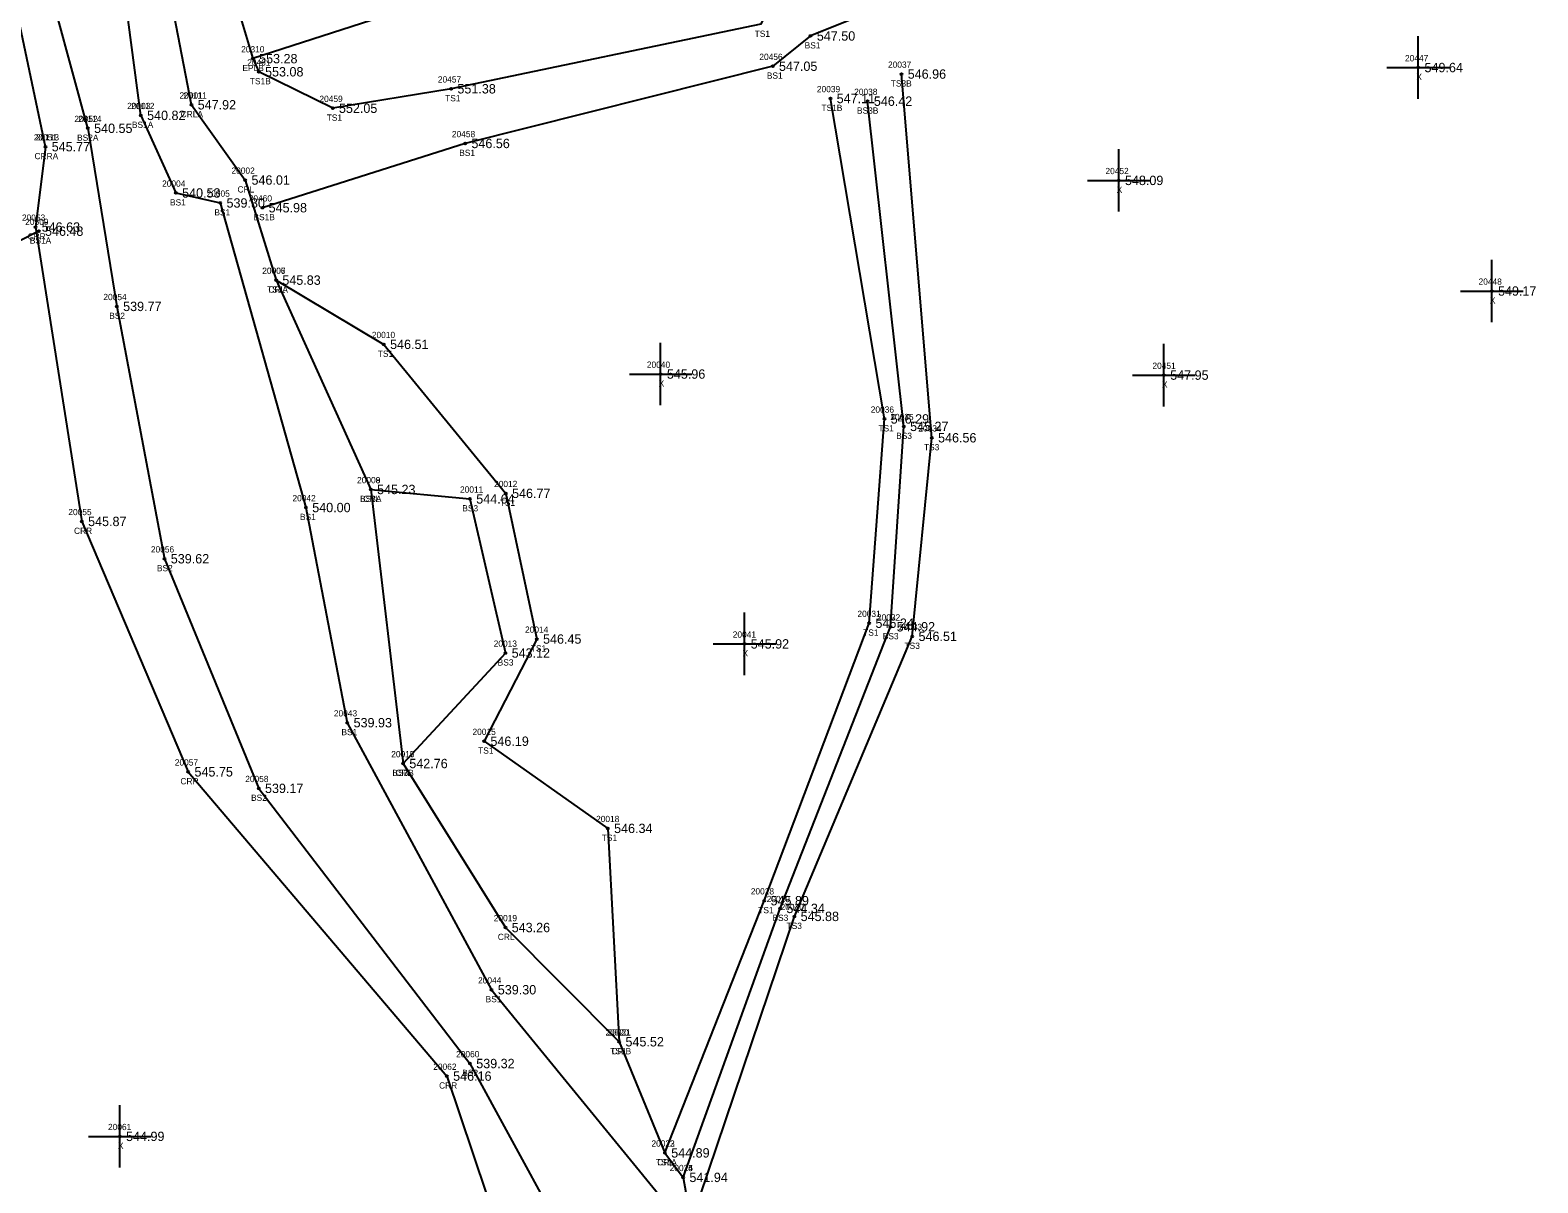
# Model space of a CAD drawing. Extents: x 1540443 to 1541844, y 887157 to 888162.
# Drawn here: x 1541136.9 to 1541377.9, y 887496.8 to 887681.2 of the extents above; entities that cross this region are included whole.
import ezdxf

# ---------------------------------------------------------------- set-up
doc = ezdxf.new("R2010")
doc.units = 0
for name, color, linetype in [('RD_DTM_BkLn2', 7, 'Continuous'), ('RD_DTM_BkLn_txCode', 7, 'Continuous'), ('RD_EX_H2O', 7, 'Continuous'), ('RD_EX_H2O_txCode', 7, 'Continuous'), ('RD_EX_Misc', 7, 'Continuous'), ('RD_EX_Misc_txCode', 7, 'Continuous'), ('RD_EX_Road', 7, 'Continuous'), ('RD_EX_Road_txCode', 7, 'Continuous'), ('RD_EX_TX_H2O_ELEV', 7, 'Continuous'), ('RD_EX_TX_Misc_ELEV', 7, 'Continuous'), ('RD_EX_TX_Road_ELEV', 7, 'Continuous'), ('RD_SMD_Locator', 7, 'Continuous')]:
    doc.layers.add(name, color=color, linetype=linetype)

msp = doc.modelspace()

# ---------------------------------------------------------------- linework, layer by layer
at = {"layer": 'RD_DTM_BkLn2'}
for points in [[(1541146.1, 887665.49), (1541138.57, 887693.18), (1541134.72, 887704.76), (1541142.18, 887722.96), (1541114.88, 887744.39), (1541098.19, 887760.21), (1541108.65, 887794.85), (1541126.24, 887822.69), (1541166.01, 887866.51), (1541149.08, 887912.73), (1541115.84, 887949.01), (1541089.41, 887986.26), (1541082.08, 888036.68), (1541064.88, 888057.53), (1541079.32, 888092.84), (1541092.39, 888127.26), (1541076.18, 888157.56)], [(1541824.97, 887864.95), (1541773.24, 887848.9), (1541728.33, 887834.59), (1541680.22, 887820.65), (1541632.2, 887806.6), (1541586.15, 887794.2), (1541535.56, 887777.78), (1541490.03, 887763.87), (1541442.11, 887749.28), (1541414.74, 887732.66), (1541394.55, 887728.51), (1541346.01, 887715.56), (1541298.68, 887704.05), (1541256.52, 887687.99), (1541253.67, 887682.12), (1541204.18, 887671.81), (1541185.24, 887668.7), (1541173.43, 887674.53)], [(1541826.01, 887862.16), (1541773.99, 887846.34), (1541729.05, 887832.97), (1541681.03, 887818.46), (1541632.94, 887804.51), (1541587.44, 887789.41), (1541536.78, 887773.27), (1541491.06, 887758.08), (1541445.99, 887740.14), (1541416.24, 887728.45), (1541395.49, 887723.75), (1541347.04, 887711.22), (1541300.85, 887696.02), (1541261.64, 887680.26), (1541255.59, 887675.42), (1541206.42, 887663.07), (1541174, 887652.79)], [(1541154.57, 887667.56), (1541150.51, 887698.19), (1541151.23, 887717.23), (1541159.67, 887729.57), (1541158.46, 887743.28), (1541175.94, 887756.06), (1541180.1, 887781.42), (1541208.84, 887815.45), (1541228.8, 887816.99), (1541237.09, 887835.99), (1541252.66, 887846.36), (1541275.47, 887851.95), (1541302.69, 887835.08), (1541351.22, 887857.05)], [(1541166.05, 887698.62), (1541166.88, 887695.38), (1541169.43, 887686.85), (1541172.48, 887676.63), (1541173.43, 887674.53)], [(1541242.57, 887490.48), (1541259.05, 887539.45), (1541277.9, 887584.24), (1541281.02, 887616), (1541276.17, 887674.17)], [(1541238.36, 887501.63), (1541254.24, 887541.96), (1541271.01, 887586.34), (1541273.45, 887619.01), (1541264.81, 887670.26)], [(1541241.27, 887497.71), (1541256.78, 887540.73), (1541274.41, 887585.77), (1541276.55, 887617.82), (1541270.76, 887669.83)], [(1541154.57, 887667.56), (1541160.17, 887655.15), (1541167.27, 887653.55), (1541180.97, 887604.84), (1541187.58, 887570.43), (1541210.64, 887527.72), (1541238.36, 887493.82), (1541248.3, 887440.2), (1541253.39, 887402.02), (1541268.17, 887373.2), (1541292.51, 887343.28), (1541305.73, 887316.29), (1541321.44, 887255.3), (1541336.42, 887224.95), (1541338.83, 887215.6), (1541353.71, 887177.71)], [(1541146.1, 887665.49), (1541150.74, 887637.01), (1541158.36, 887596.65), (1541173.42, 887559.93), (1541207.19, 887515.92), (1541227.14, 887479.24), (1541238.45, 887421.16), (1541256.87, 887373.46), (1541277.28, 887344.99), (1541292.28, 887299.84), (1541309.01, 887259.64), (1541319.98, 887221.42), (1541339.02, 887172.82)], [(1541138.25, 887649.04), (1541119.04, 887639.29), (1541108.87, 887634.52), (1541064.74, 887620.96), (1541041.79, 887616.95), (1541011.83, 887612.01), (1540975.54, 887603.81), (1540975.09, 887600.27), (1540979.83, 887576.64)], [(1541176.19, 887641.21), (1541193.42, 887630.94), (1541212.92, 887607.11), (1541217.87, 887583.81), (1541209.46, 887567.47), (1541229.23, 887553.53), (1541231.05, 887519.4)], [(1541191.34, 887607.73), (1541207.19, 887606.22), (1541212.85, 887581.57), (1541196.49, 887563.9)]]:
    msp.add_lwpolyline(points, dxfattribs=at)
at = {"layer": 'RD_EX_H2O'}
for points in [[(1541139.32, 887662.55), (1541132.94, 887692.98), (1541127.99, 887710.83), (1541127.84, 887719.69), (1541112.29, 887736.27), (1541094.28, 887759.52), (1541097.04, 887797.31), (1541106.04, 887811.91), (1541109.47, 887816.01), (1541121.03, 887830.67), (1541155.26, 887878.19), (1541140.59, 887910.22), (1541112.01, 887944.26), (1541086.28, 887983.65), (1541077.88, 888035.59), (1541062.25, 888056.78), (1541074.93, 888096.19), (1541086.66, 888128.26), (1541074.68, 888157.66)], [(1541162.66, 887669.25), (1541156.85, 887699.34), (1541155.63, 887713.65), (1541161.97, 887728.63), (1541167.93, 887745.6), (1541178.82, 887753.04), (1541184.89, 887779.89), (1541211.43, 887808.11), (1541231.17, 887813.83), (1541242.51, 887826.96), (1541257.39, 887839.59), (1541274.43, 887846.05), (1541301.1, 887832.19), (1541353.26, 887851.5)], [(1541162.66, 887669.25), (1541171.26, 887657.22), (1541176.19, 887641.21), (1541191.34, 887607.73), (1541196.49, 887563.9), (1541212.86, 887537.67), (1541231.05, 887519.4), (1541238.36, 887501.63), (1541241.27, 887497.71), (1541242.57, 887490.48), (1541255.99, 887444.22), (1541265.96, 887413.11), (1541283.07, 887379.68), (1541296.54, 887342.39), (1541310.03, 887318.77), (1541323.77, 887293.5), (1541326.83, 887277.23), (1541347.14, 887231.32), (1541343.88, 887214.13), (1541363.6, 887175.65)], [(1541139.32, 887662.55), (1541137.72, 887649.7), (1541145.14, 887602.62), (1541162.15, 887562.57), (1541203.5, 887513.91), (1541216.11, 887476.29), (1541233.11, 887419.79), (1541253.41, 887371.38), (1541273.08, 887343.25), (1541287.88, 887296.49), (1541302.23, 887257.73), (1541317.42, 887219.54), (1541335.4, 887172.24)]]:
    msp.add_lwpolyline(points, dxfattribs=at)
at = {"layer": 'RD_EX_Misc'}
for p, q in [((1541358.79, 887670.21), (1541358.79, 887680.21)), ((1541353.79, 887675.21), (1541363.79, 887675.21)), ((1541310.9, 887652.16), (1541310.9, 887662.16)), ((1541305.9, 887657.16), (1541315.9, 887657.16)), ((1541370.54, 887634.47), (1541370.54, 887644.47)), ((1541365.54, 887639.47), (1541375.54, 887639.47)), ((1541237.67, 887621.19), (1541237.67, 887631.19)), ((1541318.13, 887621.02), (1541318.13, 887631.02)), ((1541232.67, 887626.19), (1541242.67, 887626.19)), ((1541313.13, 887626.02), (1541323.13, 887626.02)), ((1541251.07, 887578.03), (1541251.07, 887588.03)), ((1541246.07, 887583.03), (1541256.07, 887583.03)), ((1541151.21, 887499.27), (1541151.21, 887509.27)), ((1541146.21, 887504.27), (1541156.21, 887504.27))]:
    msp.add_line(p, q, dxfattribs=at)
at = {"layer": 'RD_EX_Road'}
msp.add_lwpolyline([(1541823.08, 887870.08), (1541774.23, 887855.6), (1541726.64, 887841.16), (1541678.89, 887827.09), (1541630.15, 887812.57), (1541582.93, 887798.43), (1541534.59, 887784.1), (1541487.04, 887769.99), (1541438.64, 887755.66), (1541391.44, 887742.05), (1541342.36, 887727.48), (1541295.07, 887713.91), (1541246.74, 887699.66), (1541197.81, 887684.79), (1541172.48, 887676.63)], dxfattribs=at)
at = {"layer": 'RD_SMD_Locator'}
for centre in [(1541261.64, 887680.26), (1541172.48, 887676.63), (1541173.43, 887674.53), (1541255.59, 887675.42), (1541276.17, 887674.17), (1541358.79, 887675.21), (1541204.18, 887671.81), (1541162.66, 887669.25), (1541162.66, 887669.25), (1541185.24, 887668.7), (1541264.81, 887670.26), (1541270.76, 887669.83), (1541154.57, 887667.56), (1541154.57, 887667.56), (1541146.1, 887665.49), (1541146.1, 887665.49), (1541139.32, 887662.55), (1541139.32, 887662.55), (1541206.42, 887663.07), (1541171.26, 887657.22), (1541310.9, 887657.16), (1541160.17, 887655.15), (1541167.27, 887653.55), (1541174, 887652.79), (1541137.72, 887649.7), (1541138.25, 887649.04), (1541176.19, 887641.21), (1541176.19, 887641.21), (1541370.54, 887639.47), (1541150.74, 887637.01), (1541193.42, 887630.94), (1541237.67, 887626.19), (1541318.13, 887626.02), (1541273.45, 887619.01), (1541276.55, 887617.82), (1541281.02, 887616), (1541191.34, 887607.73), (1541191.34, 887607.73), (1541207.19, 887606.22), (1541212.92, 887607.11), (1541180.97, 887604.84), (1541145.14, 887602.62), (1541158.36, 887596.65), (1541271.01, 887586.34), (1541274.41, 887585.77), (1541217.87, 887583.81), (1541251.07, 887583.03), (1541277.9, 887584.24), (1541212.85, 887581.57), (1541187.58, 887570.43), (1541209.46, 887567.47), (1541196.49, 887563.9), (1541196.49, 887563.9), (1541162.15, 887562.57), (1541173.42, 887559.93), (1541229.23, 887553.53), (1541254.24, 887541.96), (1541256.78, 887540.73), (1541259.05, 887539.45), (1541212.86, 887537.67), (1541210.64, 887527.72), (1541231.05, 887519.4), (1541231.05, 887519.4), (1541207.19, 887515.92), (1541203.5, 887513.91), (1541151.21, 887504.27), (1541238.36, 887501.63), (1541238.36, 887501.63), (1541241.27, 887497.71), (1541241.27, 887497.71)]:
    msp.add_circle(centre, 0.15, dxfattribs=at)

# ---------------------------------------------------------------- texts
at = {"layer": 'RD_DTM_BkLn_txCode'}
for s, p in [('TS1', (1541252.7, 887680.12)), ('BS1', (1541260.69, 887678.26)), ('20461', (1541171.58, 887675.53)), ('20456', (1541253.45, 887676.42)), ('20037', (1541274.02, 887675.17)), ('20457', (1541202.06, 887672.81)), ('BS1', (1541254.65, 887673.42)), ('TS1B', (1541172, 887672.53)), ('20039', (1541262.65, 887671.26)), ('20038', (1541268.61, 887670.83)), ('TS3B', (1541274.46, 887672.17)), ('20003', (1541152.38, 887668.56)), ('20112', (1541153.02, 887668.56)), ('20459', (1541183.12, 887669.7)), ('TS1', (1541203.22, 887669.81)), ('TS1B', (1541263.38, 887668.26)), ('BS3B', (1541269.06, 887667.83)), ('20052', (1541143.94, 887666.49)), ('20114', (1541144.55, 887666.49)), ('BS1A', (1541153.14, 887665.56)), ('BS1A', (1541153.14, 887665.56)), ('TS1', (1541184.28, 887666.7)), ('BS2A', (1541144.38, 887663.49)), ('BS2A', (1541144.38, 887663.49)), ('20458', (1541204.3, 887664.07)), ('BS1', (1541205.47, 887661.07)), ('20004', (1541157.97, 887656.15)), ('20005', (1541165.08, 887654.55)), ('20460', (1541171.82, 887653.79)), ('BS1', (1541159.23, 887653.15)), ('BS1', (1541166.33, 887651.55)), ('20509', (1541136.09, 887650.04)), ('BS1B', (1541172.58, 887650.79)), ('BS1A', (1541136.82, 887647.04)), ('20007', (1541173.99, 887642.21)), ('TS1A', (1541174.74, 887639.21)), ('20054', (1541148.58, 887638.01)), ('BS2', (1541149.51, 887635.01)), ('20010', (1541191.5, 887631.94)), ('TS1', (1541192.46, 887628.94)), ('20036', (1541271.26, 887620.01)), ('20035', (1541274.39, 887618.82)), ('TS1', (1541272.48, 887617.01)), ('BS3', (1541275.32, 887615.82)), ('20034', (1541278.86, 887617)), ('TS3', (1541279.77, 887614)), ('20009', (1541189.14, 887608.73)), ('20012', (1541211.04, 887608.11)), ('20042', (1541178.81, 887605.84)), ('BS3A', (1541189.62, 887605.73)), ('20011', (1541205.6, 887607.22)), ('TS1', (1541211.96, 887605.11)), ('BS1', (1541180.02, 887602.84)), ('BS3', (1541205.96, 887604.22)), ('20056', (1541156.18, 887597.65)), ('BS2', (1541157.14, 887594.65)), ('20031', (1541269.13, 887587.34)), ('20032', (1541272.25, 887586.77)), ('20014', (1541215.99, 887584.81)), ('TS1', (1541270.05, 887584.34)), ('BS3', (1541273.18, 887583.77)), ('20033', (1541275.74, 887585.24)), ('20013', (1541210.98, 887582.57)), ('TS1', (1541216.91, 887581.81)), ('TS3', (1541276.66, 887582.24)), ('BS3', (1541211.62, 887579.57)), ('20043', (1541185.43, 887571.43)), ('BS1', (1541186.64, 887568.43)), ('20015', (1541207.59, 887568.47)), ('20016', (1541194.59, 887564.9)), ('TS1', (1541208.5, 887565.47)), ('BS3B', (1541194.79, 887561.9)), ('20058', (1541171.26, 887560.93)), ('BS2', (1541172.19, 887557.93)), ('20018', (1541227.35, 887554.53)), ('TS1', (1541228.27, 887551.53)), ('20028', (1541252.08, 887542.96)), ('20029', (1541254.62, 887541.73)), ('20030', (1541256.85, 887540.45)), ('TS1', (1541253.28, 887539.96)), ('BS3', (1541255.55, 887538.73)), ('TS3', (1541257.8, 887537.45)), ('20044', (1541208.48, 887528.72)), ('BS1', (1541209.69, 887525.72)), ('20020', (1541228.85, 887520.4)), ('20060', (1541204.97, 887516.92)), ('TS1B', (1541229.62, 887517.4)), ('BS2', (1541205.96, 887513.92)), ('20023', (1541236.2, 887502.63)), ('TS1A', (1541236.91, 887499.63)), ('20025', (1541239.11, 887498.71))]:
    msp.add_text(s, height=1, dxfattribs=at).set_placement(p)
at = {"layer": 'RD_EX_H2O_txCode'}
for s, p in [('20001', (1541160.75, 887670.25)), ('20111', (1541161.39, 887670.25)), ('CRLA', (1541160.94, 887667.25)), ('CRLA', (1541160.94, 887667.25)), ('20051', (1541137.45, 887663.55)), ('20113', (1541137.77, 887663.55)), ('CRRA', (1541137.58, 887660.55)), ('CRRA', (1541137.58, 887660.55)), ('20002', (1541169.06, 887658.22)), ('CRL', (1541170.03, 887655.22)), ('20053', (1541135.56, 887650.7)), ('CRR', (1541136.47, 887647.7)), ('20006', (1541173.97, 887642.21)), ('CRL', (1541174.96, 887639.21)), ('20008', (1541189.14, 887608.73)), ('CRL', (1541190.11, 887605.73)), ('20055', (1541142.98, 887603.62)), ('CRR', (1541143.89, 887600.62)), ('20017', (1541194.61, 887564.9)), ('20057', (1541160, 887563.57)), ('CRL', (1541195.26, 887561.9)), ('CRR', (1541160.9, 887560.57)), ('20019', (1541210.99, 887538.67)), ('CRL', (1541211.64, 887535.67)), ('20021', (1541229.18, 887520.4)), ('CRL', (1541229.82, 887517.4)), ('20062', (1541201.32, 887514.91)), ('CRR', (1541202.25, 887511.91)), ('20022', (1541236.2, 887502.63)), ('CRL', (1541237.13, 887499.63)), ('20024', (1541239.11, 887498.71))]:
    msp.add_text(s, height=1, dxfattribs=at).set_placement(p)
at = {"layer": 'RD_EX_Misc_txCode'}
for s, p in [('20447', (1541356.67, 887676.21)), ('X', (1541358.48, 887673.21)), ('20452', (1541308.78, 887658.16)), ('X', (1541310.58, 887655.16)), ('20448', (1541368.43, 887640.47)), ('X', (1541370.23, 887637.47)), ('20040', (1541235.47, 887627.19)), ('20451', (1541316.29, 887627.02)), ('X', (1541237.35, 887624.19)), ('X', (1541317.81, 887624.02)), ('20041', (1541249.2, 887584.03)), ('X', (1541250.76, 887581.03)), ('20061', (1541149.32, 887505.27)), ('X', (1541150.9, 887502.27))]:
    msp.add_text(s, height=1, dxfattribs=at).set_placement(p)
at = {"layer": 'RD_EX_Road_txCode'}
for s, p in [('20310', (1541170.61, 887677.63)), ('EPLB', (1541170.81, 887674.63))]:
    msp.add_text(s, height=1, dxfattribs=at).set_placement(p)
at = {"layer": 'RD_EX_TX_H2O_ELEV'}
for s, p in [('547.92', (1541163.66, 887668.5)), ('547.92', (1541163.66, 887668.5)), ('545.77', (1541140.32, 887661.8)), ('545.77', (1541140.32, 887661.8)), ('546.01', (1541172.26, 887656.47)), ('546.63', (1541138.72, 887648.95)), ('545.83', (1541177.19, 887640.46)), ('545.23', (1541192.34, 887606.98)), ('545.87', (1541146.14, 887601.87)), ('545.75', (1541163.15, 887561.82)), ('542.76', (1541197.49, 887563.15)), ('543.26', (1541213.86, 887536.92)), ('545.52', (1541232.05, 887518.65)), ('546.16', (1541204.5, 887513.16)), ('544.89', (1541239.36, 887500.88)), ('541.94', (1541242.27, 887496.96))]:
    msp.add_text(s, height=1.5, dxfattribs=at).set_placement(p)
at = {"layer": 'RD_EX_TX_Misc_ELEV'}
for s, p in [('547.50', (1541262.64, 887679.51)), ('547.05', (1541256.59, 887674.67)), ('553.08', (1541174.43, 887673.78)), ('546.96', (1541277.17, 887673.42)), ('549.64', (1541359.79, 887674.46)), ('551.38', (1541205.18, 887671.06)), ('552.05', (1541186.24, 887667.95)), ('547.11', (1541265.81, 887669.51)), ('546.42', (1541271.76, 887669.08)), ('540.82', (1541155.57, 887666.81)), ('540.82', (1541155.57, 887666.81)), ('540.55', (1541147.1, 887664.74)), ('540.55', (1541147.1, 887664.74)), ('546.56', (1541207.42, 887662.32)), ('548.09', (1541311.9, 887656.41)), ('540.53', (1541161.17, 887654.4)), ('539.30', (1541168.27, 887652.8)), ('545.98', (1541175, 887652.04)), ('546.48', (1541139.25, 887648.29)), ('545.83', (1541177.19, 887640.46)), ('549.17', (1541371.54, 887638.72)), ('539.77', (1541151.74, 887636.26)), ('546.51', (1541194.42, 887630.19)), ('545.96', (1541238.67, 887625.44)), ('547.95', (1541319.13, 887625.27)), ('546.29', (1541274.45, 887618.26)), ('545.27', (1541277.55, 887617.07)), ('546.56', (1541282.02, 887615.25)), ('545.23', (1541192.34, 887606.98)), ('544.64', (1541208.19, 887605.47)), ('546.77', (1541213.92, 887606.36)), ('540.00', (1541181.97, 887604.09)), ('539.62', (1541159.36, 887595.9)), ('546.24', (1541272.01, 887585.59)), ('546.45', (1541218.87, 887583.06)), ('544.92', (1541275.41, 887585.02)), ('546.51', (1541278.9, 887583.49)), ('543.12', (1541213.85, 887580.82)), ('545.92', (1541252.07, 887582.28)), ('539.93', (1541188.58, 887569.68)), ('546.19', (1541210.46, 887566.72)), ('542.76', (1541197.49, 887563.15)), ('539.17', (1541174.42, 887559.18)), ('546.34', (1541230.23, 887552.78)), ('545.89', (1541255.24, 887541.21)), ('544.34', (1541257.78, 887539.98)), ('545.88', (1541260.05, 887538.7)), ('539.30', (1541211.64, 887526.97)), ('545.52', (1541232.05, 887518.65)), ('539.32', (1541208.19, 887515.17)), ('544.99', (1541152.21, 887503.52)), ('544.89', (1541239.36, 887500.88)), ('541.94', (1541242.27, 887496.96))]:
    msp.add_text(s, height=1.5, dxfattribs=at).set_placement(p)
at = {"layer": 'RD_EX_TX_Road_ELEV'}
msp.add_text('553.28', height=1.5, dxfattribs=at).set_placement((1541173.48, 887675.88))

doc.saveas('drawing.dxf')
